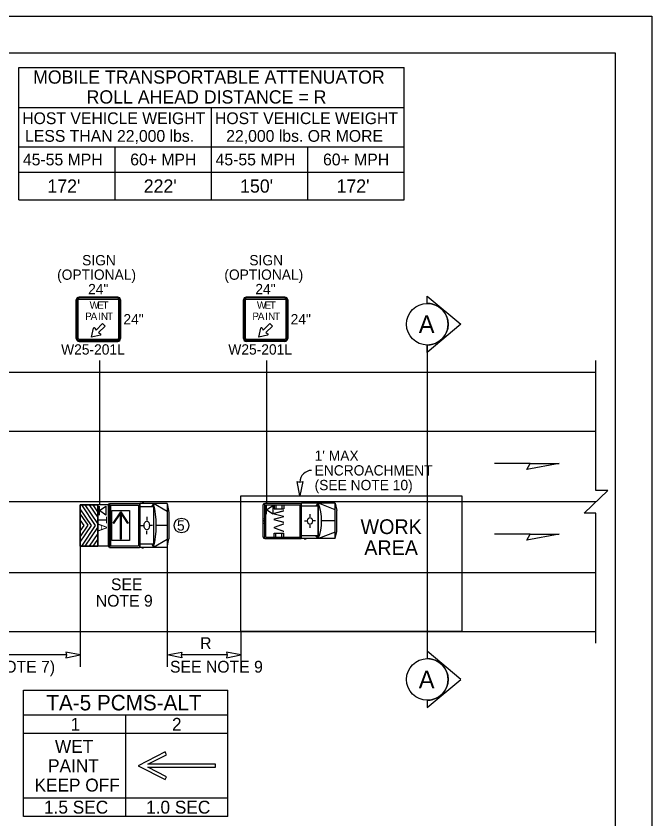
# Model space of a CAD drawing. Extents: x 0 to 17, y 0 to 11.
# Drawn here: x 12.68 to 17, y 5.55 to 11 of the extents above; entities that cross this region are included whole.
import ezdxf

# ---------------------------------------------------------------- set-up
doc = ezdxf.new("R2010")
doc.units = 0
for name, color, linetype in [('RD_ED_ShoulderPavedEdge', 7, 'Continuous'), ('RD_MK_LineEdgeWhite', 7, 'Continuous'), ('RD_MK_LineEdgeYellow', 7, 'Continuous'), ('RD_MK_LineLane', 7, 'Continuous'), ('SH_GI_PlotLimits', 7, 'Continuous'), ('SH_GI_SheetBorder3', 7, 'Continuous'), ('SH_TI_Tables', 7, 'Continuous'), ('SH_TI_WZSectionCut', 7, 'Continuous'), ('TR_SN_ConstructionSigns', 7, 'Continuous'), ('TR_SN_SignNotes', 7, 'Continuous'), ('TR_WZ_PortableChangeMessageSign', 7, 'Continuous'), ('TR_WZ_PortableSignMountBlk-Org', 7, 'Continuous'), ('TR_WZ_ProtectiveVehicle', 7, 'Continuous'), ('TR_WZ_TransportableAttenuator', 7, 'Continuous'), ('TR_WZ_WorkZoneDetails', 7, 'Continuous'), ('TR_WZ_WorkZoneTextCurrent', 7, 'Continuous')]:
    doc.layers.add(name, color=color, linetype=linetype)

msp = doc.modelspace()

# ---------------------------------------------------------------- linework, layer by layer
at = {"layer": 'RD_ED_ShoulderPavedEdge'}
for p, q in [((1.8283, 8.5807), (16.62, 8.5807)), ((1.8283, 6.8207), (16.62, 6.8207))]:
    msp.add_line(p, q, dxfattribs=at)
at = {"layer": 'RD_MK_LineEdgeWhite'}
msp.add_line((1.8283, 7.2207), (16.62, 7.2207), dxfattribs=at)
at = {"layer": 'RD_MK_LineEdgeYellow'}
msp.add_line((1.8283, 8.1807), (16.62, 8.1807), dxfattribs=at)
at = {"layer": 'RD_MK_LineLane'}
msp.add_line((16.62, 7.7007), (1.8283, 7.7007), dxfattribs=at)
at = {"layer": 'SH_GI_PlotLimits'}
msp.add_lwpolyline([(0, 11), (17, 11), (17, 0), (0, 0)], close=True, dxfattribs=at)
at = {"layer": 'SH_GI_SheetBorder3'}
for p, q in [((1, 10.75), (16.75, 10.75)), ((16.75, 10.75), (16.75, 0.25))]:
    msp.add_line(p, q, dxfattribs=at)
at = {"layer": 'SH_TI_Tables'}
for p, q in [((12.7019, 9.7515), (12.7019, 10.65)), ((12.7019, 10.65), (15.3188, 10.65)), ((15.3188, 9.7515), (15.3188, 10.65)), ((12.7019, 10.3797), (15.3188, 10.3797)), ((14.0096, 9.7515), (14.0096, 10.3797)), ((12.7019, 10.1123), (14.0096, 10.1123)), ((13.3557, 9.7515), (13.3557, 10.1123)), ((14.0096, 10.1123), (15.3188, 10.1123)), ((14.6642, 9.7515), (14.6642, 10.1123)), ((12.7019, 9.9395), (13.3557, 9.9395)), ((13.3557, 9.9395), (14.0096, 9.9395)), ((14.0096, 9.9395), (14.6642, 9.9395)), ((14.6642, 9.9395), (15.3188, 9.9395)), ((12.7019, 9.7515), (15.3188, 9.7515))]:
    msp.add_line(p, q, dxfattribs=at)
at = {"layer": 'SH_TI_WZSectionCut'}
for p, q in [((15.4753, 9.0481), (15.4753, 9.098)), ((15.4753, 9.098), (15.7034, 8.9069)), ((15.7034, 8.9069), (15.4753, 8.7158)), ((15.4753, 8.7158), (15.4753, 8.7657)), ((15.4753, 8.7657), (15.4753, 6.6358)), ((15.4753, 6.6857), (15.4753, 6.6358)), ((15.7034, 6.4945), (15.4753, 6.6857)), ((15.4753, 6.3034), (15.7034, 6.4945)), ((15.4753, 6.3533), (15.4753, 6.3034))]:
    msp.add_line(p, q, dxfattribs=at)
for centre in [(15.4753, 8.9069), (15.4753, 6.4945)]:
    msp.add_circle(centre, 0.1412, dxfattribs=at)
for centre in [(15.4753, 8.9069), (15.4753, 6.4945)]:
    msp.add_arc(centre, 0.1412, 269.9978, 90.0022, dxfattribs=at)
at = {"layer": 'TR_SN_ConstructionSigns'}
for p, q in [((13.0922, 9.072), (13.0922, 8.8095)), ((13.0922, 8.8095), (13.0922, 9.072)), ((13.0922, 9.072), (13.0922, 8.8095)), ((13.0969, 9.072), (13.0969, 8.8095)), ((13.1047, 8.8095), (13.1047, 9.072)), ((13.3735, 9.0907), (13.111, 9.0907)), ((13.111, 9.0907), (13.3735, 9.0907)), ((13.3735, 9.0907), (13.111, 9.0907)), ((13.3735, 9.086), (13.111, 9.086)), ((13.111, 9.0782), (13.3735, 9.0782)), ((13.3797, 9.072), (13.3797, 8.8095)), ((13.3875, 8.8095), (13.3875, 9.072)), ((13.3922, 8.8095), (13.3922, 9.072)), ((13.3922, 9.072), (13.3922, 8.8095)), ((13.3922, 8.8095), (13.3922, 9.072)), ((14.2274, 9.072), (14.2274, 8.8095)), ((14.2274, 8.8095), (14.2274, 9.072)), ((14.2274, 9.072), (14.2274, 8.8095)), ((14.2321, 9.072), (14.2321, 8.8095)), ((14.2399, 8.8095), (14.2399, 9.072)), ((14.5086, 9.0908), (14.2461, 9.0908)), ((14.2461, 9.0908), (14.5086, 9.0908)), ((14.5086, 9.0908), (14.2461, 9.0908)), ((14.5086, 9.0861), (14.2461, 9.0861)), ((14.2461, 9.0783), (14.5086, 9.0783)), ((14.5149, 9.072), (14.5149, 8.8095)), ((14.5227, 8.8095), (14.5227, 9.072)), ((14.5274, 8.8095), (14.5274, 9.072)), ((14.5274, 9.072), (14.5274, 8.8095)), ((14.5274, 8.8095), (14.5274, 9.072)), ((13.2262, 8.8674), (13.2704, 8.9116)), ((13.2881, 8.8939), (13.2439, 8.8497)), ((13.2704, 8.9116), (13.2881, 8.8939)), ((14.3613, 8.8674), (14.4055, 8.9116)), ((14.4232, 8.8939), (14.379, 8.8497)), ((14.4055, 8.9116), (14.4232, 8.8939)), ((13.1964, 8.8199), (13.2095, 8.8796)), ((13.218, 8.8809), (13.2262, 8.8674)), ((13.2439, 8.8497), (13.2573, 8.8416)), ((14.3315, 8.8199), (14.3447, 8.8796)), ((14.3532, 8.8809), (14.3613, 8.8674)), ((14.379, 8.8497), (14.3925, 8.8416)), ((13.3735, 8.8032), (13.111, 8.8032)), ((13.111, 8.7954), (13.3735, 8.7954)), ((13.111, 8.7907), (13.3735, 8.7907)), ((13.3735, 8.7907), (13.111, 8.7907)), ((13.111, 8.7907), (13.3735, 8.7907)), ((13.2561, 8.833), (13.1964, 8.8199)), ((14.5086, 8.8033), (14.2461, 8.8033)), ((14.2461, 8.7954), (14.5086, 8.7954)), ((14.2461, 8.7908), (14.5086, 8.7908)), ((14.5086, 8.7908), (14.2461, 8.7908)), ((14.2461, 8.7908), (14.5086, 8.7908)), ((14.3912, 8.833), (14.3315, 8.8199))]:
    msp.add_line(p, q, dxfattribs=at)
for centre, radius, start, end in [((13.111, 9.072), 0.0188, 90, 180), ((13.111, 9.072), 0.0188, 90, 180), ((13.111, 9.072), 0.0188, 90, 180), ((13.111, 9.072), 0.0141, 90, 180), ((13.111, 9.072), 0.00625, 90, 180), ((13.3735, 9.072), 0.0188, 0, 90), ((13.3735, 9.072), 0.0188, 0, 90), ((13.3735, 9.072), 0.0188, 0, 90), ((13.3735, 9.072), 0.0141, 0, 90), ((13.3735, 9.072), 0.00625, 0, 90), ((14.2461, 9.072), 0.0188, 90, 180), ((14.2461, 9.072), 0.0188, 90, 180), ((14.2461, 9.072), 0.0188, 90, 180), ((14.2461, 9.072), 0.0141, 90, 180), ((14.2461, 9.072), 0.00625, 90, 180), ((14.5086, 9.072), 0.0188, 0, 90), ((14.5086, 9.072), 0.0188, 0, 90), ((14.5086, 9.072), 0.0188, 0, 90), ((14.5086, 9.072), 0.0141, 0, 90), ((14.5086, 9.072), 0.00625, 0, 90), ((13.214, 8.8784), 0.00469, 31.1441, 165.4258), ((13.2549, 8.8376), 0.00469, 284.5742, 58.8559), ((14.3492, 8.8785), 0.00469, 31.1441, 165.4258), ((14.3901, 8.8376), 0.00469, 284.5742, 58.8559), ((13.111, 8.8095), 0.0188, 180, 270), ((13.111, 8.8095), 0.0188, 180, 270), ((13.111, 8.8095), 0.0188, 180, 270), ((13.111, 8.8095), 0.0141, 180, 270), ((13.111, 8.8095), 0.00625, 180, 270), ((13.3735, 8.8095), 0.0141, 270, 0), ((13.3735, 8.8095), 0.00625, 270, 0), ((13.3735, 8.8095), 0.0188, 270, 0), ((13.3735, 8.8095), 0.0188, 270, 0), ((13.3735, 8.8095), 0.0188, 270, 0), ((14.2461, 8.8095), 0.0188, 180, 270), ((14.2461, 8.8095), 0.0188, 180, 270), ((14.2461, 8.8095), 0.0188, 180, 270), ((14.2461, 8.8095), 0.0141, 180, 270), ((14.2461, 8.8095), 0.00625, 180, 270), ((14.5086, 8.8095), 0.0141, 270, 0), ((14.5086, 8.8095), 0.00625, 270, 0), ((14.5086, 8.8095), 0.0188, 270, 0), ((14.5086, 8.8095), 0.0188, 270, 0), ((14.5086, 8.8095), 0.0188, 270, 0)]:
    msp.add_arc(centre, radius, start, end, dxfattribs=at)
at = {"layer": 'TR_SN_SignNotes'}
msp.add_ellipse((13.5706, 7.5398), major_axis=(0, 0.0289), ratio=0.642144, dxfattribs=at)
at = {"layer": 'TR_WZ_PortableChangeMessageSign'}
for p, q in [((12.7348, 6.4207), (14.1208, 6.4207)), ((12.7348, 5.5639), (12.7348, 6.4207)), ((14.1208, 5.5639), (14.1208, 6.4207)), ((14.1208, 6.2527), (12.7348, 6.2527)), ((13.4278, 5.5639), (13.4278, 6.2527)), ((13.4278, 6.1267), (12.7348, 6.1267)), ((14.1208, 6.1267), (13.4278, 6.1267)), ((13.6958, 6.0017), (13.5118, 5.9083)), ((14.0368, 5.9188), (13.577, 5.9188)), ((13.577, 5.8978), (14.0368, 5.8978)), ((14.0368, 5.8978), (14.0368, 5.9188)), ((12.7348, 5.6899), (13.4278, 5.6899)), ((13.4278, 5.6899), (14.1208, 5.6899)), ((14.1208, 5.5639), (12.7348, 5.5639))]:
    msp.add_line(p, q, dxfattribs=at)
for points in [[(13.577, 5.9188), (13.7052, 5.9829), (13.7005, 5.9923), (13.6958, 6.0017)], [(13.5118, 5.9083), (13.6958, 5.8149), (13.7005, 5.8243), (13.7052, 5.8337), (13.577, 5.8978)]]:
    msp.add_lwpolyline(points, dxfattribs=at)
at = {"layer": 'TR_WZ_PortableSignMountBlk-Org'}
for p, q in [((13.2487, 7.611), (13.2487, 7.671)), ((14.3839, 7.6162), (14.3839, 7.6762))]:
    msp.add_line(p, q, dxfattribs=at)
for points in [[(13.2487, 7.641), (13.2918, 7.671), (13.2918, 7.611)], [(14.3839, 7.6462), (14.427, 7.6762), (14.427, 7.6162)]]:
    msp.add_lwpolyline(points, close=True, dxfattribs=at)
at = {"layer": 'TR_WZ_ProtectiveVehicle'}
for p, q in [((14.3719, 7.6908), (14.6187, 7.6908)), ((14.3719, 7.4508), (14.3719, 7.6908)), ((14.6187, 7.4508), (14.6187, 7.6908)), ((14.622, 7.4508), (14.622, 7.6908)), ((14.8487, 7.6908), (14.622, 7.6908)), ((14.653, 7.6941), (14.6394, 7.6941)), ((14.7214, 7.6722), (14.7333, 7.6908)), ((14.7333, 7.4508), (14.7333, 7.6908)), ((14.7354, 7.4508), (14.7354, 7.6908)), ((14.8487, 7.6468), (14.7354, 7.6908)), ((14.8487, 7.4508), (14.8487, 7.6908)), ((14.8487, 7.6908), (14.8599, 7.6423)), ((14.3603, 7.462), (14.3603, 7.6795)), ((14.3657, 7.6868), (14.3711, 7.6868)), ((14.3711, 7.4547), (14.3711, 7.6868)), ((14.3789, 7.4603), (14.3789, 7.6812)), ((14.3789, 7.6812), (14.6117, 7.6812)), ((14.4345, 7.6812), (14.4345, 7.6536)), ((14.4345, 7.6536), (14.5005, 7.6536)), ((14.4477, 7.6812), (14.4477, 7.6536)), ((14.4885, 7.6812), (14.4885, 7.6536)), ((14.5005, 7.6812), (14.5005, 7.6536)), ((14.6117, 7.4603), (14.6117, 7.6812)), ((14.7333, 7.6722), (14.622, 7.6722)), ((14.8599, 7.4992), (14.8599, 7.6423)), ((14.3603, 7.5877), (14.3711, 7.5832)), ((14.6781, 7.6169), (14.6784, 7.5989)), ((14.3603, 7.5539), (14.3711, 7.5584)), ((14.3632, 7.5708), (14.3682, 7.5708)), ((14.3657, 7.5674), (14.3657, 7.5741)), ((14.6419, 7.5717), (14.6597, 7.5712)), ((14.662, 7.5712), (14.662, 7.5712)), ((14.6789, 7.5232), (14.6789, 7.5426)), ((14.7151, 7.5706), (14.7, 7.5707)), ((14.8487, 7.5708), (14.7576, 7.5708)), ((14.4345, 7.4879), (14.5005, 7.4879)), ((14.4345, 7.4603), (14.4345, 7.4879)), ((14.4477, 7.4603), (14.4477, 7.4879)), ((14.4885, 7.4603), (14.4885, 7.4879)), ((14.5005, 7.4603), (14.5005, 7.4879)), ((14.8487, 7.4947), (14.7354, 7.4508)), ((14.8487, 7.4508), (14.8599, 7.4992)), ((14.3657, 7.4547), (14.3711, 7.4547)), ((14.3719, 7.4508), (14.6187, 7.4508)), ((14.3789, 7.4603), (14.6117, 7.4603)), ((14.7333, 7.4694), (14.622, 7.4694)), ((14.8487, 7.4508), (14.622, 7.4508)), ((14.653, 7.4474), (14.6394, 7.4474)), ((14.7333, 7.4508), (14.7189, 7.4694))]:
    msp.add_line(p, q, dxfattribs=at)
for centre, major_axis, start_param, end_param in [((14.5734, 7.5708), (0, 0.2518), 4.215667, 5.208926), ((14.3657, 7.6795), (0, 0.00732), 0, 1.570796), ((14.3657, 7.462), (0, -0.00732), 4.712389, 6.283185)]:
    msp.add_ellipse(centre, major_axis=major_axis, ratio=0.73155, start_param=start_param, end_param=end_param, dxfattribs=at)
for centre, major_axis in [((14.6789, 7.5708), (0, -0.0231)), ((14.3657, 7.5708), (0, -0.00338))]:
    msp.add_ellipse(centre, major_axis=major_axis, ratio=0.73155, dxfattribs=at)
at = {"layer": 'TR_WZ_TransportableAttenuator'}
for p, q in [((13.318, 7.6898), (13.5211, 7.6898)), ((13.318, 7.6898), (13.318, 7.3899)), ((13.5211, 7.6898), (13.5211, 7.3899)), ((13.5239, 7.6898), (13.5239, 7.3899)), ((13.7103, 7.6898), (13.5239, 7.6898)), ((13.5505, 7.6941), (13.5393, 7.6941)), ((13.6154, 7.6898), (13.6035, 7.6666)), ((13.6154, 7.6898), (13.6154, 7.3899)), ((13.6171, 7.6898), (13.6171, 7.3899)), ((13.7103, 7.6349), (13.6171, 7.6898)), ((13.7103, 7.6898), (13.7103, 7.3899)), ((13.7103, 7.6898), (13.7195, 7.6293)), ((13.1196, 7.6177), (13.1196, 7.6541)), ((13.1948, 7.541), (13.1196, 7.6541)), ((13.1196, 7.6541), (13.1196, 7.6177)), ((13.1274, 7.6809), (13.1529, 7.6809)), ((13.1274, 7.6809), (13.2209, 7.5401)), ((13.1529, 7.6809), (13.1274, 7.6809)), ((13.2375, 7.5525), (13.1529, 7.6809)), ((13.1805, 7.6809), (13.206, 7.6809)), ((13.206, 7.6809), (13.1805, 7.6809)), ((13.1805, 7.6809), (13.2375, 7.5941)), ((13.2375, 7.6332), (13.206, 7.6809)), ((13.318, 7.6809), (13.2375, 7.6809)), ((13.2375, 7.3994), (13.2375, 7.6809)), ((13.3085, 7.6758), (13.3085, 7.4039)), ((13.3129, 7.6849), (13.3173, 7.6849)), ((13.3173, 7.6849), (13.3173, 7.3948)), ((13.318, 7.6805), (13.318, 7.3994)), ((13.3238, 7.6779), (13.3238, 7.4019)), ((13.3238, 7.6779), (13.5154, 7.6779)), ((13.5154, 7.6779), (13.5154, 7.4019)), ((13.6154, 7.6666), (13.5239, 7.6666)), ((13.1196, 7.6177), (13.1706, 7.5414)), ((13.2375, 7.6332), (13.2375, 7.5941)), ((13.2375, 7.5941), (13.2375, 7.6332)), ((13.5707, 7.5993), (13.5706, 7.575)), ((13.7195, 7.6293), (13.7195, 7.4504)), ((13.1196, 7.5011), (13.1196, 7.5791)), ((13.1457, 7.5403), (13.1196, 7.5791)), ((13.1196, 7.5791), (13.1196, 7.5011)), ((13.1706, 7.5414), (13.1196, 7.4646)), ((13.1196, 7.4278), (13.1948, 7.541)), ((13.1196, 7.5011), (13.1457, 7.5403)), ((13.2209, 7.5401), (13.1273, 7.3992)), ((13.1524, 7.3992), (13.2375, 7.5275)), ((13.2375, 7.5525), (13.2375, 7.5275)), ((13.2375, 7.5275), (13.2375, 7.5525)), ((13.3085, 7.561), (13.3173, 7.5554)), ((13.3109, 7.5399), (13.3149, 7.5399)), ((13.3129, 7.544), (13.3129, 7.5356)), ((13.5309, 7.54), (13.5475, 7.54)), ((13.5521, 7.5393), (13.5521, 7.5393)), ((13.6103, 7.54), (13.5937, 7.54)), ((13.7103, 7.5399), (13.6354, 7.5399)), ((13.2375, 7.486), (13.1799, 7.3992)), ((13.2375, 7.486), (13.2375, 7.4446)), ((13.2375, 7.4446), (13.2375, 7.486)), ((13.3085, 7.5187), (13.3173, 7.5244)), ((13.5707, 7.4804), (13.5706, 7.5046)), ((13.1196, 7.4278), (13.1196, 7.4646)), ((13.1196, 7.4646), (13.1196, 7.4278)), ((13.2068, 7.3992), (13.2375, 7.4446)), ((13.7103, 7.4448), (13.6171, 7.3899)), ((13.7103, 7.3899), (13.7195, 7.4504)), ((13.1524, 7.3992), (13.1273, 7.3992)), ((13.1273, 7.3992), (13.1524, 7.3992)), ((13.2068, 7.3992), (13.1799, 7.3992)), ((13.1799, 7.3992), (13.2068, 7.3992)), ((13.318, 7.3994), (13.2375, 7.3994)), ((13.3129, 7.3948), (13.3173, 7.3948)), ((13.318, 7.3899), (13.5211, 7.3899)), ((13.3238, 7.4019), (13.5154, 7.4019)), ((13.6154, 7.4131), (13.5239, 7.4131)), ((13.7103, 7.3899), (13.5239, 7.3899)), ((13.5493, 7.3857), (13.5381, 7.3857)), ((13.6056, 7.4131), (13.6154, 7.3899))]:
    msp.add_line(p, q, dxfattribs=at)
for points in [[(13.2375, 7.3992), (13.1196, 7.3992), (13.1196, 7.6809), (13.2375, 7.6809)], [(13.3338, 7.6416), (13.4538, 7.6416), (13.4538, 7.438), (13.3338, 7.438)], [(13.3421, 7.5559), (13.3938, 7.6334), (13.3918, 7.6232), (13.3454, 7.5537)], [(13.3938, 7.6334), (13.3958, 7.6232), (13.3918, 7.6232)], [(13.3918, 7.4462), (13.3918, 7.6232), (13.3958, 7.6232), (13.3958, 7.4462)], [(13.3938, 7.6334), (13.4454, 7.5559), (13.4421, 7.5537), (13.3958, 7.6232)]]:
    msp.add_lwpolyline(points, close=True, dxfattribs=at)
msp.add_lwpolyline([(13.2375, 7.6809), (13.1196, 7.6809), (13.1196, 7.3992), (13.2375, 7.3994)], dxfattribs=at)
for centre, major_axis, start_param, end_param in [((13.4838, 7.5398), (0, 0.3148), 4.215852, 5.209111), ((13.3129, 7.6757), (0, 0.00915), 6.283185, 7.853982), ((13.3129, 7.4039), (0, -0.00915), 4.712389, 6.283185)]:
    msp.add_ellipse(centre, major_axis=major_axis, ratio=0.481608, start_param=start_param, end_param=end_param, dxfattribs=at)
for centre, major_axis, ratio in [((13.3129, 7.5398), (0, -0.00422), 0.481608), ((13.5706, 7.5398), (0, -0.0289), 0.642144)]:
    msp.add_ellipse(centre, major_axis=major_axis, ratio=ratio, dxfattribs=at)
at = {"layer": 'TR_WZ_WorkZoneDetails'}
for p, q in [((13.2487, 8.6607), (13.2487, 7.6809)), ((14.3839, 8.6607), (14.3839, 7.6908)), ((16.1734, 7.96), (15.9323, 7.96)), ((16.1734, 7.48), (15.9323, 7.48)), ((13.1196, 7.4092), (13.1196, 6.5807)), ((13.7103, 7.3999), (13.7103, 6.5808)), ((14.2103, 6.8207), (14.2103, 6.5808)), ((13.0259, 6.6607), (11.7135, 6.6607)), ((14.1166, 6.6608), (13.8041, 6.6608))]:
    msp.add_line(p, q, dxfattribs=at)
msp.add_lwpolyline([(16.62, 6.7407), (16.62, 7.6233), (16.5399, 7.6233), (16.7, 7.7782), (16.62, 7.7782), (16.62, 8.6607)], dxfattribs=at)
for points in [[(16.37, 7.96), (16.1512, 7.9214), (16.1734, 7.96)], [(14.6101, 7.7407), (14.5908, 7.839), (14.6101, 7.8345), (14.6294, 7.839)], [(14.2103, 6.8207), (14.2103, 7.7407), (15.7103, 7.7407), (15.7103, 6.8207)], [(16.37, 7.48), (16.1512, 7.4414), (16.1734, 7.48)], [(13.1196, 6.6607), (13.0213, 6.68), (13.0259, 6.6607), (13.0213, 6.6415)], [(13.7103, 6.6608), (13.8086, 6.68), (13.8041, 6.6608), (13.8086, 6.6415)], [(14.2103, 6.6608), (14.1121, 6.68), (14.1166, 6.6608), (14.1121, 6.6415)]]:
    msp.add_lwpolyline(points, close=True, dxfattribs=at)
msp.add_circle((13.8064, 7.5399), 0.05, dxfattribs=at)
msp.add_arc((14.692, 7.8325), 0.082, 91.3481, 178.6519, dxfattribs=at)

# ---------------------------------------------------------------- texts
at = {"layer": 'SH_TI_Tables'}
for s, height, p in [('MOBILE TRANSPORTABLE ATTENUATOR', 0.09, (12.7989, 10.5408)), ('ROLL AHEAD DISTANCE = R', 0.09, (13.1619, 10.4058)), ('HOST VEHICLE WEIGHT', 0.08, (12.7254, 10.266)), ('HOST VEHICLE WEIGHT', 0.08, (14.0339, 10.266)), ('LESS THAN 22,000 lbs.', 0.08, (12.7445, 10.146)), ('22,000 lbs. OR MORE', 0.08, (14.1101, 10.146)), ('45-55 MPH', 0.08, (12.73, 9.9859)), ('60+ MPH', 0.08, (13.4585, 9.9859)), ('45-55 MPH', 0.08, (14.0381, 9.9859)), ('60+ MPH', 0.08, (14.7673, 9.9859)), ("172'", 0.09, (12.8963, 9.8005)), ("222'", 0.09, (13.5502, 9.8005)), ("150'", 0.09, (14.2044, 9.8005)), ("172'", 0.09, (14.859, 9.8005))]:
    msp.add_text(s, height=height, rotation=360, dxfattribs=at).set_placement(p)
at = {"layer": 'SH_TI_WZSectionCut'}
for rotation, p in [(359.99, (15.4171, 8.8469)), (0.01, (15.4171, 6.4345))]:
    msp.add_text('A', height=0.12, rotation=rotation, dxfattribs=at).set_placement(p)
at = {"layer": 'TR_SN_ConstructionSigns'}
for s, height, p in [('SIGN', 0.07, (13.1319, 9.3067)), ('SIGN', 0.07, (14.267, 9.3068)), ('(OPTIONAL)', 0.07, (12.9621, 9.2087)), ('(OPTIONAL)', 0.07, (14.0973, 9.2088)), ('24"', 0.07, (13.1727, 9.1107)), ('24"', 0.07, (14.3079, 9.1108)), ('W', 0.05, (13.1832, 9.0116)), ('E', 0.05, (13.2352, 9.0116)), ('T', 0.05, (13.2702, 9.0116)), ('W', 0.05, (14.3184, 9.0116)), ('E', 0.05, (14.3704, 9.0116)), ('T', 0.05, (14.4054, 9.0116)), ('P', 0.05, (13.1525, 8.9366)), ('A', 0.05, (13.1895, 8.9366)), ('I', 0.05, (13.2395, 8.9366)), ('N', 0.05, (13.2595, 8.9366)), ('T', 0.05, (13.301, 8.9366)), ('24"', 0.07, (13.4122, 8.9057)), ('P', 0.05, (14.2876, 8.9366)), ('A', 0.05, (14.3246, 8.9366)), ('I', 0.05, (14.3746, 8.9366)), ('N', 0.05, (14.3946, 8.9366)), ('T', 0.05, (14.4361, 8.9366)), ('24"', 0.07, (14.5474, 8.9058)), ('W25-201L', 0.07, (12.9894, 8.7007)), ('W25-201L', 0.07, (14.1245, 8.7008))]:
    msp.add_text(s, height=height, dxfattribs=at).set_placement(p)
at = {"layer": 'TR_WZ_PortableChangeMessageSign'}
for s, height, p in [('TA-5 PCMS-ALT', 0.105, (12.8891, 6.2842)), ('1', 0.0875, (13.0539, 6.146)), ('2', 0.0875, (13.7419, 6.146)), ('WET', 0.0875, (12.9476, 5.9958)), ('PAINT', 0.0875, (12.9005, 5.8646)), ('KEEP OFF', 0.0875, (12.8087, 5.7333)), ('1.5 SEC', 0.0875, (12.8731, 5.5832)), ('1.0 SEC', 0.0875, (13.5661, 5.5832))]:
    msp.add_text(s, height=height, rotation=360, dxfattribs=at).set_placement(p)
at = {"layer": 'TR_WZ_ProtectiveVehicle'}
msp.add_text('WV', height=0.07, rotation=270, dxfattribs=at).set_placement((14.4325, 7.6449))
at = {"layer": 'TR_WZ_TransportableAttenuator'}
msp.add_text('TA', height=0.06, rotation=270, dxfattribs=at).set_placement((13.2416, 7.6021))
at = {"layer": 'TR_WZ_WorkZoneDetails'}
for s, height, p in [('WORK', 0.1, (15.0218, 7.482)), ('5', 0.07, (13.7757, 7.5049)), ('AREA', 0.1, (15.0473, 7.3395))]:
    msp.add_text(s, height=height, dxfattribs=at).set_placement(p)
at = {"layer": 'TR_WZ_WorkZoneTextCurrent'}
for s, height, p in [("1' MAX", 0.07, (14.7101, 7.9792)), ('ENCROACHMENT', 0.07, (14.7101, 7.8795)), ('(SEE NOTE 10)', 0.07, (14.7101, 7.7797)), ('SEE', 0.08, (13.3275, 7.1007)), ('NOTE 9', 0.08, (13.2247, 6.9887)), ('R', 0.08, (13.9327, 6.7008)), ('(VARIES, SEE NOTE 7)', 0.08, (11.795, 6.5407)), ('SEE NOTE 9', 0.08, (13.7285, 6.5408))]:
    msp.add_text(s, height=height, dxfattribs=at).set_placement(p)

doc.saveas('drawing.dxf')
